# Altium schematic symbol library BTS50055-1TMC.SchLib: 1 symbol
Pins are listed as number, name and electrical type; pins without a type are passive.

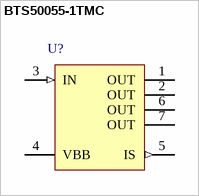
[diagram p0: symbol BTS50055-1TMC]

## BTS50055-1TMC
designator U?
Smart Highside High Current Power Switch Reversave, 1 Channel, 17 A Load Current, -40 to 150 degC, PG-TO220-7-4, Reel, Green; Manufacturer: Infineon; PartNumber: BTS50055-1TMC; Channels: 1; Green: TRUE; Group: Automotive Qualified; Load Current (typ): 17 A; Ptot (max): 170 W; Recommended Operating Voltage Max.: 34 V; Recommended Operating Voltage Min.: 5.5 V; RON @ 25degreesC: 6 mOhm; RON(max) @ 150degreesC: 10.5 mOhm; toff (max): 200 us; ton (max): 470 us
footprint INF-PG-TO220-7-4_N (DPAK, 7-Leads, Body 10x9.25mm, Pitch 1.27mm, IPC Medium Density)
footprint INF-PG-TO220-7-4_L (DPAK, 7-Leads, Body 10x9.25mm, Pitch 1.27mm, IPC High Density)
footprint INF-PG-TO220-7-4_M (DPAK, 7-Leads, Body 10x9.25mm, Pitch 1.27mm, IPC Low Density)
pins: 1 OUT (power) "Output to the load. The pins1,2,6 and 7 must be shorted with each other especially in high current applications!", 2 OUT (power) "Output to the load. The pins1,2,6 and 7 must be shorted with each other especially in high current applications!", 3 IN (in) "Input, activates the power switch in case of short to ground", 4 VBB (power) "Positive power supply voltage, the tab is electrically connected to this pin. In high current applications the tab should be used for the Vbb connection instead of this pin", 5 IS (out) "Diagnostic feedback providing a sense current proportional to the load current; zero current on failure (see Truth Table on page 7)", 6 OUT (power) "Output to the load. The pins1,2,6 and 7 must be shorted with each other especially in high current applications!", 7 OUT (power) "Output to the load. The pins1,2,6 and 7 must be shorted with each other especially in high current applications!"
